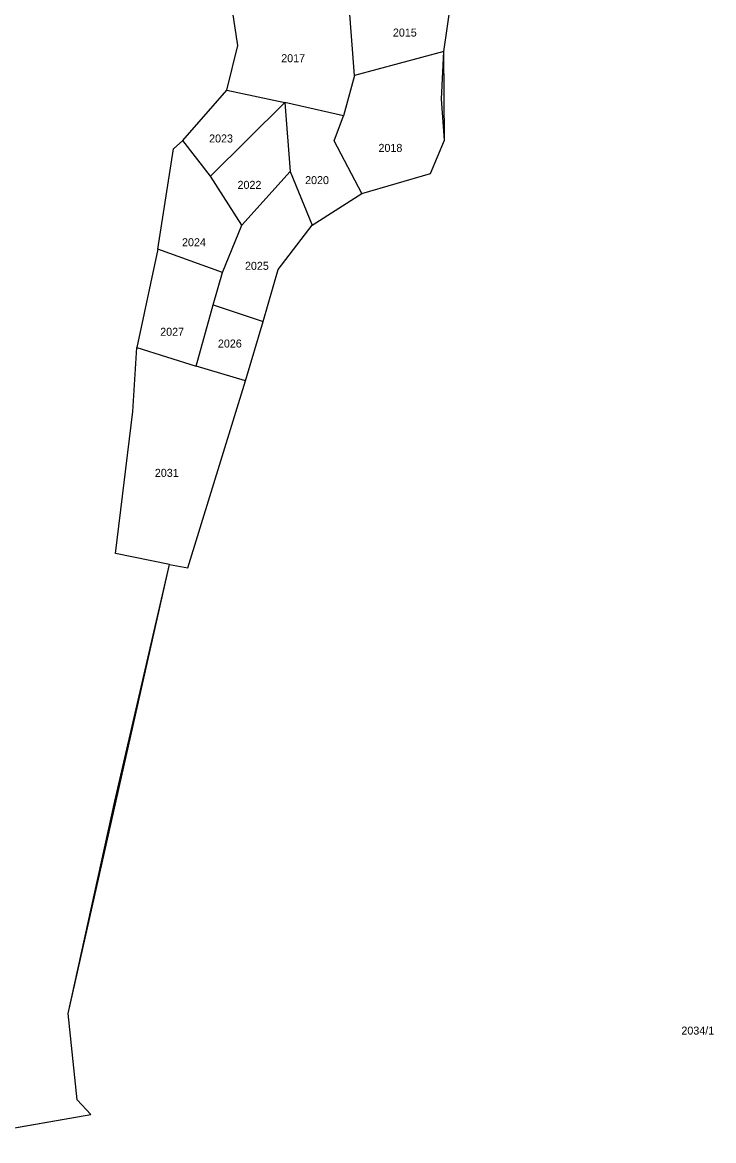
# Model space of a CAD drawing. Extents: x -581999 to -572728, y -1219553 to -1212032.
# Drawn here: x -577960.1 to -577787.4, y -1216296.7 to -1216017.4 of the extents above; entities that cross this region are included whole.
import ezdxf

# ---------------------------------------------------------------- set-up
doc = ezdxf.new("R2010")
doc.units = 0
for name, color, linetype in [('Vrstva 1', 7, 'Continuous'), ('Vrstva 2', 7, 'Continuous'), ('Vrstva 63', 7, 'Continuous')]:
    doc.layers.add(name, color=color, linetype=linetype)

msp = doc.modelspace()

# ---------------------------------------------------------------- linework, layer by layer
at = {"layer": 'Vrstva 1'}
for points in [[(-577908.988, -1216034.275), (-577906.298, -1216023.171), (-577907.622, -1216014.439)], [(-577877.155, -1216030.671), (-577878.496, -1216013.127)], [(-577854.772, -1216024.692), (-577853.043, -1216012.586)], [(-577854.772, -1216024.692), (-577877.155, -1216030.671)], [(-577875.318, -1216060.115), (-577858.146, -1216055.098), (-577854.651, -1216046.765), (-577854.772, -1216024.692)], [(-577877.155, -1216030.671), (-577879.885, -1216040.751)], [(-577920.006, -1216046.852), (-577908.988, -1216034.275)], [(-577908.988, -1216034.275), (-577894.532, -1216037.4)], [(-577913.096, -1216055.83), (-577894.532, -1216037.4)], [(-577894.532, -1216037.4), (-577893.232, -1216054.661)], [(-577879.885, -1216040.751), (-577894.532, -1216037.4)], [(-577875.318, -1216060.115), (-577882.217, -1216046.953), (-577879.885, -1216040.751)], [(-577926.253, -1216073.993), (-577922.327, -1216048.982), (-577920.006, -1216046.852)], [(-577913.096, -1216055.83), (-577920.006, -1216046.852)], [(-577905.225, -1216068.058), (-577913.096, -1216055.83)], [(-577905.225, -1216068.058), (-577893.232, -1216054.661)], [(-577893.232, -1216054.661), (-577887.68, -1216068.048)], [(-577887.68, -1216068.048), (-577875.318, -1216060.115)], [(-577910.07, -1216079.831), (-577905.225, -1216068.058)], [(-577899.894, -1216092.104), (-577896.193, -1216079.12), (-577887.68, -1216068.048)], [(-577926.253, -1216073.993), (-577931.527, -1216098.609)], [(-577910.07, -1216079.831), (-577926.253, -1216073.993)], [(-577912.407, -1216087.97), (-577910.07, -1216079.831)], [(-577916.692, -1216103.278), (-577912.407, -1216087.97)], [(-577912.407, -1216087.97), (-577899.894, -1216092.104)], [(-577904.359, -1216106.94), (-577899.894, -1216092.104)], [(-577923.354, -1216152.76), (-577936.843, -1216150.035), (-577932.504, -1216114.575), (-577931.527, -1216098.609)], [(-577931.527, -1216098.609), (-577916.692, -1216103.278)], [(-577904.359, -1216106.94), (-577916.692, -1216103.278)], [(-577923.354, -1216152.76), (-577918.756, -1216153.625), (-577904.359, -1216106.94)], [(-577980.317, -1216296.705), (-577942.961, -1216290.149), (-577946.419, -1216286.472), (-577948.676, -1216264.916), (-577936.971, -1216211.877), (-577923.354, -1216152.76)]]:
    msp.add_lwpolyline(points, dxfattribs=at)
at = {"layer": 'Vrstva 63'}
for p, q in [((-577854.772, -1216024.692), (-577853.043, -1216012.586)), ((-577855.381, -1216036.553), (-577854.772, -1216024.692)), ((-577854.651, -1216046.765), (-577855.381, -1216036.553)), ((-577858.146, -1216055.098), (-577854.651, -1216046.765)), ((-577875.318, -1216060.115), (-577858.146, -1216055.098)), ((-577887.68, -1216068.048), (-577875.318, -1216060.115)), ((-577896.193, -1216079.12), (-577887.68, -1216068.048)), ((-577899.894, -1216092.104), (-577896.193, -1216079.12)), ((-577904.359, -1216106.94), (-577899.894, -1216092.104)), ((-577918.756, -1216153.625), (-577904.359, -1216106.94)), ((-577948.676, -1216264.916), (-577923.354, -1216152.76)), ((-577923.354, -1216152.76), (-577918.756, -1216153.625)), ((-577946.419, -1216286.472), (-577948.676, -1216264.916)), ((-577942.961, -1216290.149), (-577946.419, -1216286.472)), ((-577980.317, -1216296.705), (-577942.961, -1216290.149))]:
    msp.add_line(p, q, dxfattribs=at)

# ---------------------------------------------------------------- texts
at = {"layer": 'Vrstva 2'}
for s, p in [('2015', (-577867.526, -1216020.92)), ('2017', (-577895.419, -1216027.328)), ('2023', (-577913.432, -1216047.376)), ('2018', (-577871.127, -1216049.732)), ('2022', (-577906.332, -1216058.962)), ('2020', (-577889.46, -1216057.784)), ('2024', (-577920.196, -1216073.298)), ('2025', (-577904.478, -1216079.189)), ('2027', (-577925.65, -1216095.666)), ('2026', (-577911.232, -1216098.602)), ('2031', (-577926.984, -1216130.902)), ('2034/1', (-577795.473, -1216270.218))]:
    msp.add_text(s, height=2, dxfattribs=at).set_placement(p)

doc.saveas('drawing.dxf')
